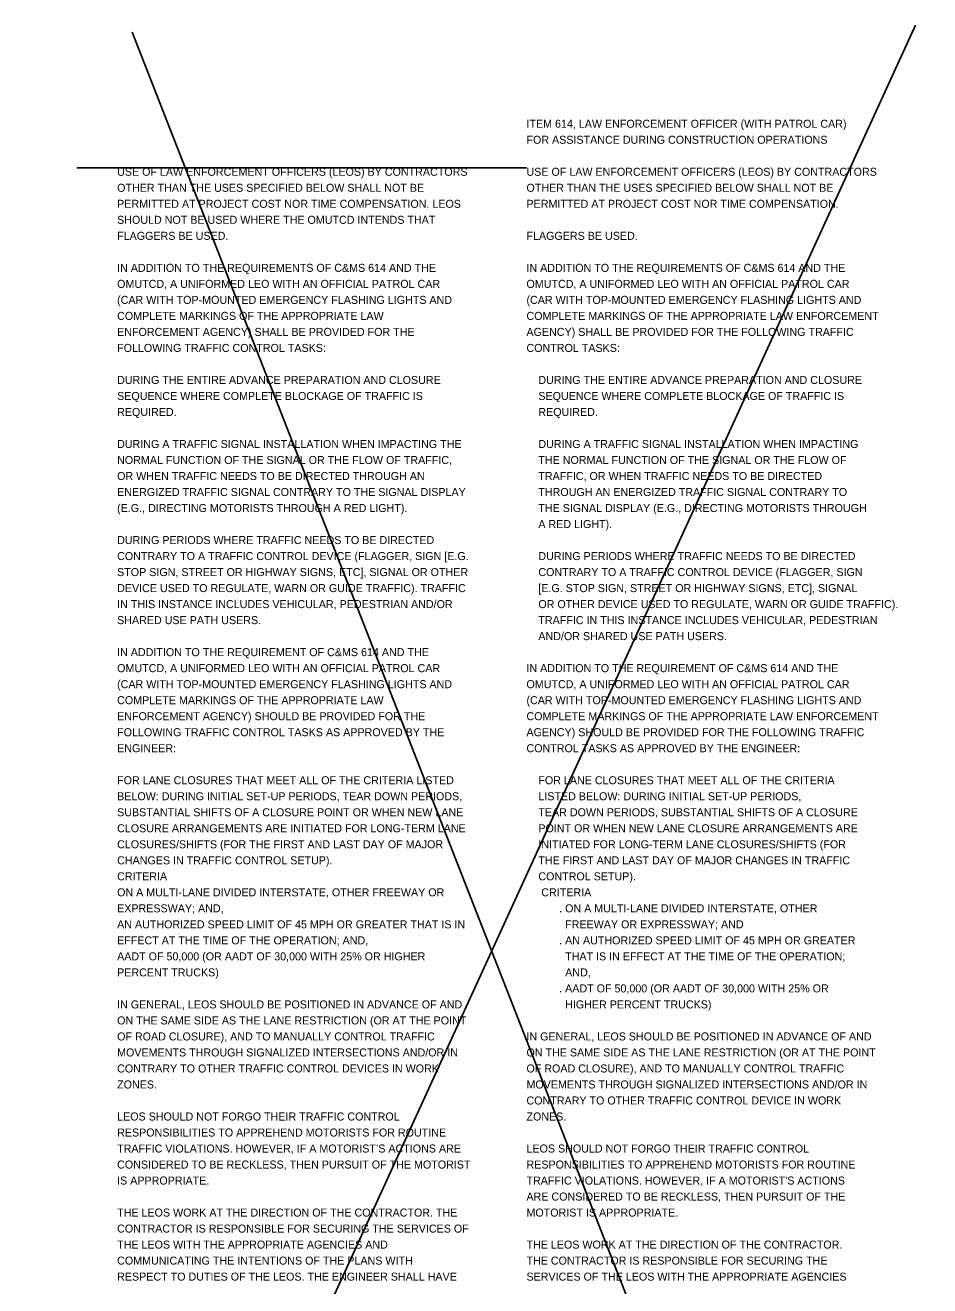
# Model space of a CAD drawing. Extents: x -18.5 to 46, y -14.2 to 42.5.
# Drawn here: x -18.54 to -2.73, y -0.05 to 22 of the extents above; entities that cross this region are included whole.
import ezdxf

# ---------------------------------------------------------------- set-up
doc = ezdxf.new("R2010")
doc.units = 0
doc.layers.add('SN_X_Public', color=7, linetype='Continuous')

msp = doc.modelspace()

# ---------------------------------------------------------------- linework, layer by layer
at = {"layer": 'SN_X_Public'}
for p, q in [((-2.978, 21.996), (-18.545, -12.023)), ((-16.677, 21.872), (-2.729, -13.768)), ((-9.781, 19.503), (-17.64, 19.503))]:
    msp.add_line(p, q, dxfattribs=at)

# ---------------------------------------------------------------- texts
for s, p in [('ITEM 614, LAW ENFORCEMENT OFFICER (WITH PATROL CAR)', (-9.781, 20.203)), ('FOR ASSISTANCE DURING CONSTRUCTION OPERATIONS', (-9.781, 19.923)), ('USE OF LAW ENFORCEMENT OFFICERS (LEOS) BY CONTRACTORS ', (-16.938, 19.363)), ('USE OF LAW ENFORCEMENT OFFICERS (LEOS) BY CONTRACTORS', (-9.781, 19.363)), ('OTHER THAN THE USES SPECIFIED BELOW SHALL NOT BE ', (-16.938, 19.083)), ('OTHER THAN THE USES SPECIFIED BELOW SHALL NOT BE', (-9.781, 19.083)), ('PERMITTED AT PROJECT COST NOR TIME COMPENSATION. LEOS ', (-16.938, 18.803)), ('PERMITTED AT PROJECT COST NOR TIME COMPENSATION.', (-9.781, 18.803)), ('SHOULD NOT BE USED WHERE THE OMUTCD INTENDS THAT ', (-16.938, 18.523)), ('FLAGGERS BE USED. ', (-16.938, 18.243)), ('FLAGGERS BE USED.', (-9.781, 18.243)), ('IN ADDITION TO THE REQUIREMENTS OF C&MS 614 AND THE ', (-16.938, 17.683)), ('IN ADDITION TO THE REQUIREMENTS OF C&MS 614 AND THE', (-9.781, 17.683)), ('OMUTCD, A UNIFORMED LEO WITH AN OFFICIAL PATROL CAR ', (-16.938, 17.403)), ('OMUTCD, A UNIFORMED LEO WITH AN OFFICIAL PATROL CAR', (-9.781, 17.403)), ('(CAR WITH TOP-MOUNTED EMERGENCY FLASHING LIGHTS AND ', (-16.938, 17.123)), ('(CAR WITH TOP-MOUNTED EMERGENCY FLASHING LIGHTS AND', (-9.781, 17.123)), ('COMPLETE MARKINGS OF THE APPROPRIATE LAW ', (-16.938, 16.843)), ('COMPLETE MARKINGS OF THE APPROPRIATE LAW ENFORCEMENT', (-9.781, 16.843)), ('ENFORCEMENT AGENCY) SHALL BE PROVIDED FOR THE ', (-16.938, 16.563)), ('AGENCY) SHALL BE PROVIDED FOR THE FOLLOWING TRAFFIC', (-9.781, 16.563)), ('FOLLOWING TRAFFIC CONTROL TASKS:', (-16.938, 16.283)), ('CONTROL TASKS:', (-9.781, 16.283)), ('DURING THE ENTIRE ADVANCE PREPARATION AND CLOSURE ', (-16.938, 15.723)), ('    DURING THE ENTIRE ADVANCE PREPARATION AND CLOSURE', (-9.781, 15.723)), ('SEQUENCE WHERE COMPLETE BLOCKAGE OF TRAFFIC IS ', (-16.938, 15.443)), ('    SEQUENCE WHERE COMPLETE BLOCKAGE OF TRAFFIC IS', (-9.781, 15.443)), ('REQUIRED.', (-16.938, 15.163)), ('    REQUIRED.', (-9.781, 15.163)), ('DURING A TRAFFIC SIGNAL INSTALLATION WHEN IMPACTING THE ', (-16.938, 14.603)), ('    DURING A TRAFFIC SIGNAL INSTALLATION WHEN IMPACTING', (-9.781, 14.603)), ('NORMAL FUNCTION OF THE SIGNAL OR THE FLOW OF TRAFFIC, ', (-16.938, 14.323)), ('    THE NORMAL FUNCTION OF THE SIGNAL OR THE FLOW OF', (-9.781, 14.323)), ('OR WHEN TRAFFIC NEEDS TO BE DIRECTED THROUGH AN ', (-16.938, 14.043)), ('    TRAFFIC, OR WHEN TRAFFIC NEEDS TO BE DIRECTED', (-9.781, 14.043)), ('ENERGIZED TRAFFIC SIGNAL CONTRARY TO THE SIGNAL DISPLAY ', (-16.938, 13.763)), ('    THROUGH AN ENERGIZED TRAFFIC SIGNAL CONTRARY TO', (-9.781, 13.763)), ('(E.G., DIRECTING MOTORISTS THROUGH A RED LIGHT).', (-16.938, 13.483)), ('    THE SIGNAL DISPLAY (E.G., DIRECTING MOTORISTS THROUGH', (-9.781, 13.483)), ('    A RED LIGHT).', (-9.781, 13.203)), ('DURING PERIODS WHERE TRAFFIC NEEDS TO BE DIRECTED ', (-16.938, 12.923)), ('CONTRARY TO A TRAFFIC CONTROL DEVICE (FLAGGER, SIGN [E.G. ', (-16.938, 12.643)), ('    DURING PERIODS WHERE TRAFFIC NEEDS TO BE DIRECTED', (-9.781, 12.643)), ('STOP SIGN, STREET OR HIGHWAY SIGNS, ETC], SIGNAL OR OTHER ', (-16.938, 12.363)), ('    CONTRARY TO A TRAFFIC CONTROL DEVICE (FLAGGER, SIGN', (-9.781, 12.363)), ('DEVICE USED TO REGULATE, WARN OR GUIDE TRAFFIC). TRAFFIC ', (-16.938, 12.083)), ('    [E.G. STOP SIGN, STREET OR HIGHWAY SIGNS, ETC], SIGNAL', (-9.781, 12.083)), ('IN THIS INSTANCE INCLUDES VEHICULAR, PEDESTRIAN AND/OR ', (-16.938, 11.803)), ('    OR OTHER DEVICE USED TO REGULATE, WARN OR GUIDE TRAFFIC).', (-9.781, 11.803)), ('SHARED USE PATH USERS. ', (-16.938, 11.523)), ('    TRAFFIC IN THIS INSTANCE INCLUDES VEHICULAR, PEDESTRIAN', (-9.781, 11.523)), ('    AND/OR SHARED USE PATH USERS.', (-9.781, 11.243)), ('IN ADDITION TO THE REQUIREMENT OF C&MS 614 AND THE ', (-16.938, 10.963)), ('OMUTCD, A UNIFORMED LEO WITH AN OFFICIAL PATROL CAR ', (-16.938, 10.683)), ('IN ADDITION TO THE REQUIREMENT OF C&MS 614 AND THE', (-9.781, 10.683)), ('(CAR WITH TOP-MOUNTED EMERGENCY FLASHING LIGHTS AND ', (-16.938, 10.403)), ('OMUTCD, A UNIFORMED LEO WITH AN OFFICIAL PATROL CAR', (-9.781, 10.403)), ('COMPLETE MARKINGS OF THE APPROPRIATE LAW ', (-16.938, 10.123)), ('(CAR WITH TOP-MOUNTED EMERGENCY FLASHING LIGHTS AND', (-9.781, 10.123)), ('ENFORCEMENT AGENCY) SHOULD BE PROVIDED FOR THE ', (-16.938, 9.843)), ('COMPLETE MARKINGS OF THE APPROPRIATE LAW ENFORCEMENT', (-9.781, 9.843)), ('FOLLOWING TRAFFIC CONTROL TASKS AS APPROVED BY THE ', (-16.938, 9.563)), ('AGENCY) SHOULD BE PROVIDED FOR THE FOLLOWING TRAFFIC', (-9.781, 9.563)), ('ENGINEER:', (-16.938, 9.283)), ('CONTROL TASKS AS APPROVED BY THE ENGINEER:', (-9.781, 9.283)), ('FOR LANE CLOSURES THAT MEET ALL OF THE CRITERIA LISTED ', (-16.938, 8.723)), ('    FOR LANE CLOSURES THAT MEET ALL OF THE CRITERIA', (-9.781, 8.723)), ('BELOW: DURING INITIAL SET-UP PERIODS, TEAR DOWN PERIODS, ', (-16.938, 8.443)), ('    LISTED BELOW: DURING INITIAL SET-UP PERIODS,', (-9.781, 8.443)), ('SUBSTANTIAL SHIFTS OF A CLOSURE POINT OR WHEN NEW LANE ', (-16.938, 8.163)), ('    TEAR DOWN PERIODS, SUBSTANTIAL SHIFTS OF A CLOSURE', (-9.781, 8.163)), ('CLOSURE ARRANGEMENTS ARE INITIATED FOR LONG-TERM LANE ', (-16.938, 7.883)), ('    POINT OR WHEN NEW LANE CLOSURE ARRANGEMENTS ARE', (-9.781, 7.883)), ('CLOSURES/SHIFTS (FOR THE FIRST AND LAST DAY OF MAJOR ', (-16.938, 7.603)), ('    INITIATED FOR LONG-TERM LANE CLOSURES/SHIFTS (FOR', (-9.781, 7.603)), ('CHANGES IN TRAFFIC CONTROL SETUP).', (-16.938, 7.323)), ('    THE FIRST AND LAST DAY OF MAJOR CHANGES IN TRAFFIC', (-9.781, 7.323)), ('CRITERIA', (-16.938, 7.043)), ('    CONTROL SETUP).', (-9.781, 7.043)), ('ON A MULTI-LANE DIVIDED INTERSTATE, OTHER FREEWAY OR ', (-16.938, 6.763)), ('     CRITERIA', (-9.781, 6.763)), ('EXPRESSWAY; AND,', (-16.938, 6.483)), ('           . ON A MULTI-LANE DIVIDED INTERSTATE, OTHER', (-9.781, 6.483)), ('AN AUTHORIZED SPEED LIMIT OF 45 MPH OR GREATER THAT IS IN ', (-16.938, 6.203)), ('             FREEWAY OR EXPRESSWAY; AND', (-9.781, 6.203)), ('EFFECT AT THE TIME OF THE OPERATION; AND,', (-16.938, 5.923)), ('           . AN AUTHORIZED SPEED LIMIT OF 45 MPH OR GREATER', (-9.781, 5.923)), ('AADT OF 50,000 (OR AADT OF 30,000 WITH 25% OR HIGHER ', (-16.938, 5.643)), ('             THAT IS IN EFFECT AT THE TIME OF THE OPERATION;', (-9.781, 5.643)), ('PERCENT TRUCKS)', (-16.938, 5.363)), ('             AND,', (-9.781, 5.363)), ('           . AADT OF 50,000 (OR AADT OF 30,000 WITH 25% OR', (-9.781, 5.083)), ('IN GENERAL, LEOS SHOULD BE POSITIONED IN ADVANCE OF AND ', (-16.938, 4.803)), ('             HIGHER PERCENT TRUCKS)', (-9.781, 4.803)), ('ON THE SAME SIDE AS THE LANE RESTRICTION (OR AT THE POINT ', (-16.938, 4.523)), ('OF ROAD CLOSURE), AND TO MANUALLY CONTROL TRAFFIC ', (-16.938, 4.243)), ('IN GENERAL, LEOS SHOULD BE POSITIONED IN ADVANCE OF AND', (-9.781, 4.243)), ('MOVEMENTS THROUGH SIGNALIZED INTERSECTIONS AND/OR IN ', (-16.938, 3.963)), ('ON THE SAME SIDE AS THE LANE RESTRICTION (OR AT THE POINT', (-9.781, 3.963)), ('CONTRARY TO OTHER TRAFFIC CONTROL DEVICES IN WORK ', (-16.938, 3.683)), ('OF ROAD CLOSURE), AND TO MANUALLY CONTROL TRAFFIC', (-9.781, 3.683)), ('ZONES.', (-16.938, 3.403)), ('MOVEMENTS THROUGH SIGNALIZED INTERSECTIONS AND/OR IN', (-9.781, 3.403)), ('CONTRARY TO OTHER TRAFFIC CONTROL DEVICE IN WORK', (-9.781, 3.123)), ('LEOS SHOULD NOT FORGO THEIR TRAFFIC CONTROL ', (-16.938, 2.843)), ('ZONES.', (-9.781, 2.843)), ('RESPONSIBILITIES TO APPREHEND MOTORISTS FOR ROUTINE ', (-16.938, 2.563)), ('TRAFFIC VIOLATIONS. HOWEVER, IF A MOTORIST’S ACTIONS ARE ', (-16.938, 2.283)), ('LEOS SHOULD NOT FORGO THEIR TRAFFIC CONTROL', (-9.781, 2.283)), ('CONSIDERED TO BE RECKLESS, THEN PURSUIT OF THE MOTORIST ', (-16.938, 2.003)), ('RESPONSIBILITIES TO APPREHEND MOTORISTS FOR ROUTINE', (-9.781, 2.003)), ('IS APPROPRIATE.', (-16.938, 1.723)), ("TRAFFIC VIOLATIONS. HOWEVER, IF A MOTORIST'S ACTIONS", (-9.781, 1.723)), ('ARE CONSIDERED TO BE RECKLESS, THEN PURSUIT OF THE', (-9.781, 1.443)), ('THE LEOS WORK AT THE DIRECTION OF THE CONTRACTOR. THE ', (-16.938, 1.163)), ('MOTORIST IS APPROPRIATE.', (-9.781, 1.163)), ('CONTRACTOR IS RESPONSIBLE FOR SECURING THE SERVICES OF ', (-16.938, 0.883)), ('THE LEOS WITH THE APPROPRIATE AGENCIES AND ', (-16.938, 0.603)), ('THE LEOS WORK AT THE DIRECTION OF THE CONTRACTOR.', (-9.781, 0.603)), ('COMMUNICATING THE INTENTIONS OF THE PLANS WITH ', (-16.938, 0.323)), ('THE CONTRACTOR IS RESPONSIBLE FOR SECURING THE', (-9.781, 0.323)), ('RESPECT TO DUTIES OF THE LEOS. THE ENGINEER SHALL HAVE ', (-16.938, 0.043)), ('SERVICES OF THE LEOS WITH THE APPROPRIATE AGENCIES', (-9.781, 0.043))]:
    msp.add_text(s, height=0.14, dxfattribs=at).set_placement(p)

doc.saveas('drawing.dxf')
